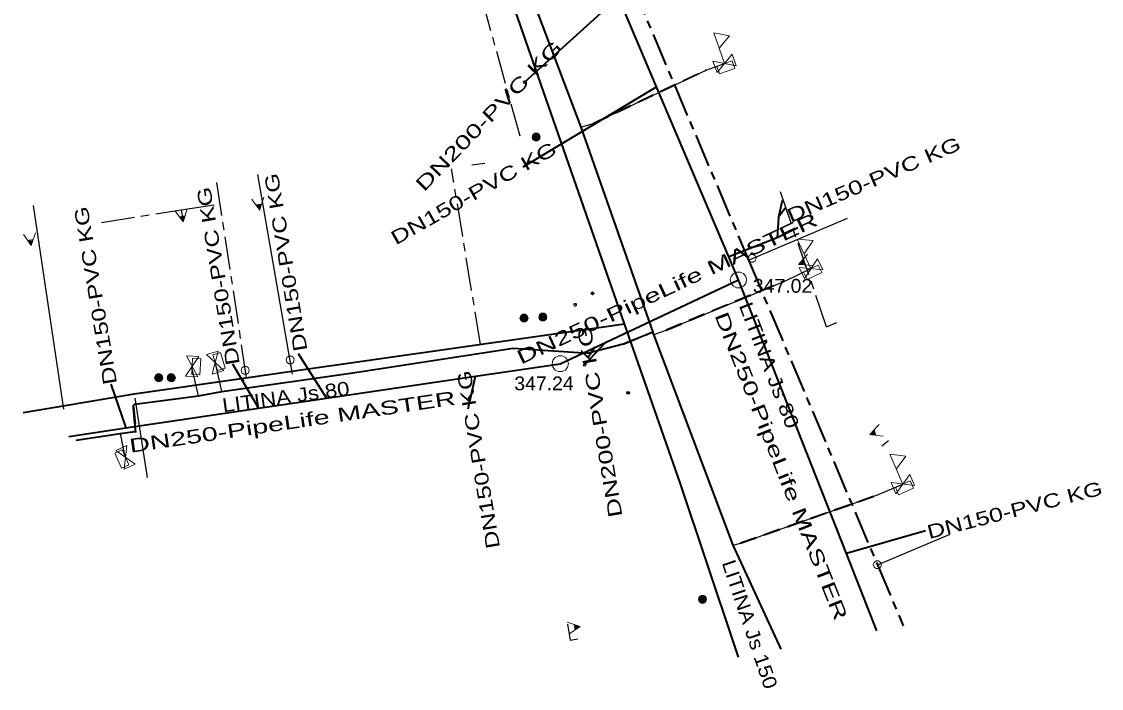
# Model space of a CAD drawing. Extents: x -763495 to -763378, y -1031793 to -1031652.
# Drawn here: x -763444.2 to -763377.8, y -1031792.8 to -1031751.8 of the extents above; entities that cross this region are included whole.
import ezdxf
from ezdxf.enums import TextEntityAlignment as Align

# ---------------------------------------------------------------- set-up
doc = ezdxf.new("R2010")
doc.units = 0
doc.header["$LTSCALE"] = 0.34
doc.header["$PDMODE"] = 32
doc.header["$PDSIZE"] = 0.17
for name, pattern in [('LONG_DASH_SHORT_DASH', [9.9, 6, -1.2, 1.5, -1.2]), ('LONG_DASHED', [7.5, 6, -1.5]), ('MEDIUM_DASHED', [4.5, 3, -1.5])]:
    doc.linetypes.add(name, pattern=pattern)
for name, color, linetype, lineweight in [('33', 7, 'Continuous', 13), ('34', 7, 'Continuous', 13), ('35', 7, 'Continuous', 13), ('37', 7, 'Continuous', 13), ('43', 7, 'Continuous', 25), ('44', 7, 'Continuous', 35), ('45', 7, 'Continuous', 13), ('47', 7, 'LONG_DASH_SHORT_DASH', 25), ('51', 7, 'LONG_DASH_SHORT_DASH', 25), ('59', 7, 'LONG_DASHED', 13)]:
    doc.layers.add(name, color=color, linetype=linetype, lineweight=lineweight)
doc.layers.add('50', color=7, linetype='Continuous')

msp = doc.modelspace()

# ---------------------------------------------------------------- linework, layer by layer
at = {"layer": '33'}
for points in [[(-763399.225, -1031766.08), (-763399.1, -1031766.17), (-763399.05, -1031766.315), (-763399.1, -1031766.46), (-763399.225, -1031766.55), (-763399.38, -1031766.55), (-763399.505, -1031766.46), (-763399.555, -1031766.315), (-763399.505, -1031766.17), (-763399.38, -1031766.08)], [(-763430.405, -1031772.97), (-763430.28, -1031773.06), (-763430.23, -1031773.205), (-763430.28, -1031773.35), (-763430.405, -1031773.44), (-763430.56, -1031773.44), (-763430.685, -1031773.35), (-763430.735, -1031773.205), (-763430.685, -1031773.06), (-763430.56, -1031772.97)], [(-763427.635, -1031772.33), (-763427.51, -1031772.42), (-763427.46, -1031772.565), (-763427.51, -1031772.71), (-763427.635, -1031772.8), (-763427.79, -1031772.8), (-763427.915, -1031772.71), (-763427.965, -1031772.565), (-763427.915, -1031772.42), (-763427.79, -1031772.33)], [(-763391.515, -1031784.93), (-763391.39, -1031785.02), (-763391.34, -1031785.165), (-763391.39, -1031785.31), (-763391.515, -1031785.4), (-763391.67, -1031785.4), (-763391.795, -1031785.31), (-763391.845, -1031785.165), (-763391.795, -1031785.02), (-763391.67, -1031784.93)]]:
    msp.add_lwpolyline(points, close=True, dxfattribs=at)
at = {"layer": '34'}
for points in [[(-763413.205, -1031755.496), (-763413.259, -1031755.565), (-763413.345, -1031755.55), (-763413.377, -1031755.466), (-763413.323, -1031755.397), (-763413.237, -1031755.412)], [(-763400.023, -1031767.161), (-763399.823, -1031767.256), (-763399.683, -1031767.431), (-763399.633, -1031767.646), (-763399.683, -1031767.861), (-763399.823, -1031768.036), (-763400.023, -1031768.131), (-763400.248, -1031768.131), (-763400.448, -1031768.036), (-763400.588, -1031767.861), (-763400.638, -1031767.646), (-763400.588, -1031767.431), (-763400.448, -1031767.256), (-763400.248, -1031767.161)], [(-763410.986, -1031772.313), (-763410.786, -1031772.408), (-763410.646, -1031772.583), (-763410.596, -1031772.798), (-763410.646, -1031773.013), (-763410.786, -1031773.188), (-763410.986, -1031773.283), (-763411.211, -1031773.283), (-763411.411, -1031773.188), (-763411.551, -1031773.013), (-763411.601, -1031772.798), (-763411.551, -1031772.583), (-763411.411, -1031772.408), (-763411.211, -1031772.313)], [(-763409.563, -1031772.788), (-763409.508, -1031772.856), (-763409.542, -1031772.937), (-763409.631, -1031772.949), (-763409.686, -1031772.882), (-763409.652, -1031772.801)]]:
    msp.add_lwpolyline(points, close=True, dxfattribs=at)
at = {"layer": '35'}
for points in [[(-763400.992, -1031754.326), (-763401.659, -1031752.44), (-763400.691, -1031752.628), (-763401.325, -1031753.383)], [(-763395.676, -1031766.945), (-763396.528, -1031765.135), (-763395.546, -1031765.226), (-763396.102, -1031766.04)], [(-763390.029, -1031780.201), (-763390.826, -1031778.367), (-763389.847, -1031778.487), (-763390.428, -1031779.284)]]:
    msp.add_lwpolyline(points, dxfattribs=at)
for points in [[(-763401.706, -1031754.181), (-763401.456, -1031754.888), (-763400.528, -1031753.764), (-763400.278, -1031754.471)], [(-763396.401, -1031766.872), (-763396.082, -1031767.55), (-763395.27, -1031766.34), (-763394.951, -1031767.018)], [(-763432.144, -1031772.024), (-763432.862, -1031772.239), (-763431.786, -1031773.221), (-763432.504, -1031773.436)], [(-763433.335, -1031772.35), (-763434.084, -1031772.313), (-763433.396, -1031773.599), (-763434.145, -1031773.562)], [(-763437.923, -1031779.28), (-763437.241, -1031778.968), (-763438.443, -1031778.144), (-763437.761, -1031777.832)], [(-763390.752, -1031780.106), (-763390.453, -1031780.794), (-763389.605, -1031779.608), (-763389.306, -1031780.296)]]:
    msp.add_lwpolyline(points, close=True, dxfattribs=at)
at = {"layer": '37'}
for points in [[(-763412.655, -1031758.62), (-763412.5, -1031758.62), (-763412.375, -1031758.71), (-763412.325, -1031758.855), (-763412.375, -1031759), (-763412.5, -1031759.09), (-763412.655, -1031759.09), (-763412.78, -1031759), (-763412.83, -1031758.855), (-763412.78, -1031758.71), (-763412.655, -1031758.62), (-763412.64, -1031758.64), (-763412.52, -1031758.64), (-763412.44, -1031758.68), (-763412.72, -1031758.68), (-763412.76, -1031758.72), (-763412.4, -1031758.72), (-763412.4, -1031758.76), (-763412.76, -1031758.76), (-763412.78, -1031758.8), (-763412.38, -1031758.8), (-763412.36, -1031758.84), (-763412.8, -1031758.84), (-763412.8, -1031758.88), (-763412.36, -1031758.88), (-763412.375, -1031758.92), (-763412.78, -1031758.92), (-763412.775, -1031758.96), (-763412.37, -1031758.96), (-763412.395, -1031759), (-763412.755, -1031759), (-763412.715, -1031759.04), (-763412.435, -1031759.04), (-763412.49, -1031759.08), (-763412.66, -1031759.08)], [(-763429.34, -1031762.549), (-763429.548, -1031763.222), (-763429.587, -1031763.35), (-763430.001, -1031762.78), (-763430.08, -1031762.671)], [(-763429.817, -1031763.033), (-763429.472, -1031762.976), (-763429.503, -1031763.001), (-763429.779, -1031763.047), (-763429.733, -1031763.08), (-763429.516, -1031763.044), (-763429.53, -1031763.087), (-763429.727, -1031763.12), (-763429.701, -1031763.156), (-763429.548, -1031763.13), (-763429.556, -1031763.172), (-763429.674, -1031763.192), (-763429.648, -1031763.228), (-763429.564, -1031763.214), (-763429.582, -1031763.258), (-763429.622, -1031763.264), (-763429.595, -1031763.301)], [(-763434.04, -1031763.28), (-763434.25, -1031763.952), (-763434.289, -1031764.08), (-763434.702, -1031763.509), (-763434.78, -1031763.4)], [(-763434.518, -1031763.763), (-763434.173, -1031763.707), (-763434.204, -1031763.732), (-763434.481, -1031763.777), (-763434.435, -1031763.81), (-763434.218, -1031763.775), (-763434.231, -1031763.817), (-763434.428, -1031763.85), (-763434.402, -1031763.886), (-763434.249, -1031763.861), (-763434.258, -1031763.903), (-763434.376, -1031763.922), (-763434.35, -1031763.958), (-763434.266, -1031763.945), (-763434.284, -1031763.988), (-763434.324, -1031763.995), (-763434.298, -1031764.031)], [(-763443.369, -1031764.738), (-763443.594, -1031765.406), (-763443.637, -1031765.533), (-763444.035, -1031764.952), (-763444.111, -1031764.842)], [(-763443.858, -1031765.21), (-763443.511, -1031765.162), (-763443.543, -1031765.187), (-763443.821, -1031765.225), (-763443.776, -1031765.259), (-763443.558, -1031765.229), (-763443.572, -1031765.271), (-763443.77, -1031765.299), (-763443.745, -1031765.336), (-763443.591, -1031765.315), (-763443.601, -1031765.356), (-763443.719, -1031765.373), (-763443.694, -1031765.41), (-763443.61, -1031765.398), (-763443.629, -1031765.441), (-763443.669, -1031765.446), (-763443.643, -1031765.483)], [(-763395.611, -1031766.758), (-763396.313, -1031766.7), (-763396.446, -1031766.688), (-763395.978, -1031766.162), (-763395.889, -1031766.062)], [(-763396.186, -1031766.396), (-763396.056, -1031766.721), (-763396.088, -1031766.696), (-763396.192, -1031766.436), (-763396.214, -1031766.488), (-763396.133, -1031766.692), (-763396.177, -1031766.688), (-763396.251, -1031766.503), (-763396.281, -1031766.536), (-763396.224, -1031766.68), (-763396.266, -1031766.681), (-763396.311, -1031766.57), (-763396.341, -1031766.603), (-763396.309, -1031766.682), (-763396.355, -1031766.674), (-763396.37, -1031766.636), (-763396.4, -1031766.67)], [(-763413.405, -1031769.76), (-763413.25, -1031769.76), (-763413.125, -1031769.85), (-763413.075, -1031769.995), (-763413.125, -1031770.14), (-763413.25, -1031770.23), (-763413.405, -1031770.23), (-763413.53, -1031770.14), (-763413.58, -1031769.995), (-763413.53, -1031769.85), (-763413.405, -1031769.76), (-763413.39, -1031769.78), (-763413.27, -1031769.78), (-763413.19, -1031769.82), (-763413.47, -1031769.82), (-763413.51, -1031769.86), (-763413.15, -1031769.86), (-763413.15, -1031769.9), (-763413.51, -1031769.9), (-763413.53, -1031769.94), (-763413.13, -1031769.94), (-763413.11, -1031769.98), (-763413.55, -1031769.98), (-763413.55, -1031770.02), (-763413.11, -1031770.02), (-763413.125, -1031770.06), (-763413.53, -1031770.06), (-763413.525, -1031770.1), (-763413.12, -1031770.1), (-763413.145, -1031770.14), (-763413.505, -1031770.14), (-763413.465, -1031770.18), (-763413.185, -1031770.18), (-763413.24, -1031770.22), (-763413.41, -1031770.22)], [(-763412.245, -1031769.69), (-763412.09, -1031769.69), (-763411.965, -1031769.78), (-763411.915, -1031769.925), (-763411.965, -1031770.07), (-763412.09, -1031770.16), (-763412.245, -1031770.16), (-763412.37, -1031770.07), (-763412.42, -1031769.925), (-763412.37, -1031769.78), (-763412.245, -1031769.69), (-763412.23, -1031769.71), (-763412.11, -1031769.71), (-763412.03, -1031769.75), (-763412.31, -1031769.75), (-763412.35, -1031769.79), (-763411.99, -1031769.79), (-763411.99, -1031769.83), (-763412.35, -1031769.83), (-763412.37, -1031769.87), (-763411.97, -1031769.87), (-763411.95, -1031769.91), (-763412.39, -1031769.91), (-763412.39, -1031769.95), (-763411.95, -1031769.95), (-763411.965, -1031769.99), (-763412.37, -1031769.99), (-763412.365, -1031770.03), (-763411.96, -1031770.03), (-763411.985, -1031770.07), (-763412.345, -1031770.07), (-763412.305, -1031770.11), (-763412.025, -1031770.11), (-763412.08, -1031770.15), (-763412.25, -1031770.15)], [(-763435.875, -1031773.43), (-763435.72, -1031773.43), (-763435.595, -1031773.52), (-763435.545, -1031773.665), (-763435.595, -1031773.81), (-763435.72, -1031773.9), (-763435.875, -1031773.9), (-763436, -1031773.81), (-763436.05, -1031773.665), (-763436, -1031773.52), (-763435.875, -1031773.43), (-763435.86, -1031773.45), (-763435.74, -1031773.45), (-763435.66, -1031773.49), (-763435.94, -1031773.49), (-763435.98, -1031773.53), (-763435.62, -1031773.53), (-763435.62, -1031773.57), (-763435.98, -1031773.57), (-763436, -1031773.61), (-763435.6, -1031773.61), (-763435.58, -1031773.65), (-763436.02, -1031773.65), (-763436.02, -1031773.69), (-763435.58, -1031773.69), (-763435.595, -1031773.73), (-763436, -1031773.73), (-763435.995, -1031773.77), (-763435.59, -1031773.77), (-763435.615, -1031773.81), (-763435.975, -1031773.81), (-763435.935, -1031773.85), (-763435.655, -1031773.85), (-763435.71, -1031773.89), (-763435.88, -1031773.89)], [(-763435.105, -1031773.43), (-763434.95, -1031773.43), (-763434.825, -1031773.52), (-763434.775, -1031773.665), (-763434.825, -1031773.81), (-763434.95, -1031773.9), (-763435.105, -1031773.9), (-763435.23, -1031773.81), (-763435.28, -1031773.665), (-763435.23, -1031773.52), (-763435.105, -1031773.43), (-763435.09, -1031773.45), (-763434.97, -1031773.45), (-763434.89, -1031773.49), (-763435.17, -1031773.49), (-763435.21, -1031773.53), (-763434.85, -1031773.53), (-763434.85, -1031773.57), (-763435.21, -1031773.57), (-763435.23, -1031773.61), (-763434.83, -1031773.61), (-763434.81, -1031773.65), (-763435.25, -1031773.65), (-763435.25, -1031773.69), (-763434.81, -1031773.69), (-763434.825, -1031773.73), (-763435.23, -1031773.73), (-763435.225, -1031773.77), (-763434.82, -1031773.77), (-763434.845, -1031773.81), (-763435.205, -1031773.81), (-763435.165, -1031773.85), (-763434.885, -1031773.85), (-763434.94, -1031773.89), (-763435.11, -1031773.89)], [(-763391.233, -1031777.253), (-763391.932, -1031777.17), (-763392.065, -1031777.155), (-763391.58, -1031776.644), (-763391.487, -1031776.547)], [(-763391.796, -1031776.871), (-763391.677, -1031777.2), (-763391.708, -1031777.174), (-763391.803, -1031776.911), (-763391.827, -1031776.962), (-763391.752, -1031777.169), (-763391.796, -1031777.164), (-763391.864, -1031776.976), (-763391.895, -1031777.008), (-763391.842, -1031777.154), (-763391.885, -1031777.153), (-763391.926, -1031777.04), (-763391.957, -1031777.073), (-763391.928, -1031777.153), (-763391.974, -1031777.143), (-763391.988, -1031777.105), (-763392.018, -1031777.138)], [(-763402.425, -1031787.05), (-763402.27, -1031787.05), (-763402.145, -1031787.14), (-763402.095, -1031787.285), (-763402.145, -1031787.43), (-763402.27, -1031787.52), (-763402.425, -1031787.52), (-763402.55, -1031787.43), (-763402.6, -1031787.285), (-763402.55, -1031787.14), (-763402.425, -1031787.05), (-763402.41, -1031787.07), (-763402.29, -1031787.07), (-763402.21, -1031787.11), (-763402.49, -1031787.11), (-763402.53, -1031787.15), (-763402.17, -1031787.15), (-763402.17, -1031787.19), (-763402.53, -1031787.19), (-763402.55, -1031787.23), (-763402.15, -1031787.23), (-763402.13, -1031787.27), (-763402.57, -1031787.27), (-763402.57, -1031787.31), (-763402.13, -1031787.31), (-763402.145, -1031787.35), (-763402.55, -1031787.35), (-763402.545, -1031787.39), (-763402.14, -1031787.39), (-763402.165, -1031787.43), (-763402.525, -1031787.43), (-763402.485, -1031787.47), (-763402.205, -1031787.47), (-763402.26, -1031787.51), (-763402.43, -1031787.51)], [(-763410.667, -1031788.699), (-763409.996, -1031788.915), (-763409.869, -1031788.957), (-763410.444, -1031789.363), (-763410.553, -1031789.441)], [(-763410.188, -1031789.183), (-763410.241, -1031788.837), (-763410.216, -1031788.868), (-763410.174, -1031789.145), (-763410.14, -1031789.099), (-763410.173, -1031788.882), (-763410.131, -1031788.896), (-763410.101, -1031789.093), (-763410.064, -1031789.067), (-763410.088, -1031788.914), (-763410.046, -1031788.923), (-763410.028, -1031789.042), (-763409.991, -1031789.016), (-763410.004, -1031788.932), (-763409.961, -1031788.95), (-763409.955, -1031788.99), (-763409.918, -1031788.964)]]:
    msp.add_lwpolyline(points, dxfattribs=at)
at = {"layer": '43', "linetype": 'LONG_DASH_SHORT_DASH'}
for p, q in [((-763416.002, -1031771.613), (-763417.782, -1031760.8)), ((-763430.39, -1031773.66), (-763432.22, -1031761.62))]:
    msp.add_line(p, q, dxfattribs=at)
at = {"layer": '43'}
for p, q in [((-763427.57, -1031773.45), (-763429.71, -1031761.15)), ((-763441.64, -1031775.59), (-763443.5, -1031763.07)), ((-763399.52, -1031766.42), (-763393.43, -1031763.84)), ((-763430.56, -1031773.91), (-763430.59, -1031773.69)), ((-763437.27, -1031774.92), (-763436.5, -1031779.792)), ((-763391.59, -1031785.17), (-763387.11, -1031783.28))]:
    msp.add_line(p, q, dxfattribs=at)
at = {"layer": '43', "lineweight": 35}
for points in [[(-763400.132, -1031790.86), (-763400.38, -1031790.12), (-763403.73, -1031780.13), (-763407.14, -1031770.35), (-763416.343, -1031743.922), (-763410.726, -1031739.937), (-763410.479, -1031739.762)], [(-763444.127, -1031775.807), (-763441.67, -1031775.39), (-763437.31, -1031774.66), (-763430.59, -1031773.69), (-763427.6, -1031773.26), (-763407.14, -1031770.35)]]:
    msp.add_lwpolyline(points, dxfattribs=at)
at = {"layer": '43', "linetype": 'LONG_DASH_SHORT_DASH', "lineweight": 35}
msp.add_lwpolyline([(-763410.726, -1031739.937), (-763410.61, -1031740.22), (-763406.7, -1031749.44), (-763399.52, -1031766.42), (-763391.59, -1031785.17), (-763390, -1031788.925)], dxfattribs=at)
at = {"layer": '44'}
for p, q in [((-763413.291, -1031755.481), (-763407.519, -1031750.23)), ((-763413.385, -1031760.681), (-763405.172, -1031755.763)), ((-763397.266, -1031763.229), (-763397.674, -1031763.789)), ((-763409.597, -1031772.869), (-763408.309, -1031771.488)), ((-763427.23, -1031772.166), (-763425.477, -1031774.924)), ((-763431.26, -1031772.812), (-763429.652, -1031775.541)), ((-763416.771, -1031775.575), (-763416.317, -1031773.57)), ((-763438.74, -1031774.059), (-763437.823, -1031776.75)), ((-763388.634, -1031783.087), (-763393.492, -1031784.483))]:
    msp.add_line(p, q, dxfattribs=at)
for points in [[(-763391.618, -1031789.234), (-763393.492, -1031784.483), (-763400.133, -1031767.646), (-763400.737, -1031766.222), (-763405.172, -1031755.763), (-763407.519, -1031750.23), (-763407.897, -1031749.337), (-763411.012, -1031744.81), (-763417.435, -1031735.477), (-763425.031, -1031724.437), (-763457.995, -1031686.981)], [(-763397.452, -1031762.75), (-763397.674, -1031763.789), (-763397.755, -1031765.048)], [(-763396.479, -1031764.447), (-763397.755, -1031765.048), (-763400.737, -1031766.222)], [(-763441.329, -1031777.268), (-763437.823, -1031776.75), (-763429.652, -1031775.541), (-763425.477, -1031774.924), (-763416.317, -1031773.57), (-763411.096, -1031772.798), (-763400.133, -1031767.646)]]:
    msp.add_lwpolyline(points, dxfattribs=at)
at = {"layer": '45', "linetype": 'MEDIUM_DASHED'}
for p, q in [((-763409.096, -1031757.994), (-763402.137, -1031754.694)), ((-763409.079, -1031758.03), (-763402.12, -1031754.73)), ((-763409.062, -1031758.066), (-763402.103, -1031754.766)), ((-763404.595, -1031770.693), (-763397.305, -1031767.673)), ((-763404.58, -1031770.73), (-763397.29, -1031767.71)), ((-763404.565, -1031770.767), (-763397.275, -1031767.747)), ((-763407.245, -1031771.563), (-763405.704, -1031770.933)), ((-763407.23, -1031771.6), (-763405.689, -1031770.97)), ((-763407.215, -1031771.637), (-763405.674, -1031771.007)), ((-763437.393, -1031775.48), (-763437.27, -1031776.862)), ((-763437.348, -1031775.476), (-763437.225, -1031776.858)), ((-763437.303, -1031775.472), (-763437.18, -1031776.854)), ((-763400.032, -1031783.802), (-763391.633, -1031780.852)), ((-763400.019, -1031783.84), (-763391.62, -1031780.89)), ((-763400.006, -1031783.878), (-763391.607, -1031780.928))]:
    msp.add_line(p, q, dxfattribs=at)
at = {"layer": '45', "lineweight": 35}
for points in [[(-763414.95, -1031744.87), (-763414.41, -1031746.14), (-763409.84, -1031758.25), (-763405.4, -1031770.86)], [(-763405.4, -1031770.86), (-763405.689, -1031770.97), (-763407.23, -1031771.6), (-763409.364, -1031772.149)], [(-763397.504, -1031790.358), (-763400.46, -1031783.97), (-763405.337, -1031771.01), (-763405.4, -1031770.86)], [(-763440.885, -1031777.5), (-763438.168, -1031777.084), (-763437.275, -1031776.978), (-763437.209, -1031776.997), (-763437.225, -1031776.858), (-763437.348, -1031775.476), (-763437.37, -1031775.391), (-763437.273, -1031775.284), (-763433.36, -1031774.772), (-763431.913, -1031774.504), (-763423.866, -1031773.351), (-763414, -1031771.837), (-763409.364, -1031772.149)]]:
    msp.add_lwpolyline(points, dxfattribs=at)
at = {"layer": '45', "lineweight": 25}
for points in [[(-763409.84, -1031758.25), (-763409.079, -1031758.03), (-763402.12, -1031754.73), (-763400.992, -1031754.326)], [(-763405.337, -1031771.01), (-763404.58, -1031770.73), (-763397.29, -1031767.71), (-763395.676, -1031766.945)], [(-763433.36, -1031774.772), (-763433.748, -1031773.104), (-763433.74, -1031772.956)], [(-763431.913, -1031774.504), (-763432.286, -1031772.855), (-763432.324, -1031772.73)], [(-763438.168, -1031777.084), (-763437.903, -1031778.424), (-763437.842, -1031778.556)], [(-763400.46, -1031783.97), (-763400.019, -1031783.84), (-763391.62, -1031780.89), (-763390.029, -1031780.201)]]:
    msp.add_lwpolyline(points, dxfattribs=at)
at = {"layer": '45'}
for points in [[(-763400.992, -1031754.326), (-763400.521, -1031754.159), (-763400.353, -1031754.63), (-763401.296, -1031754.965), (-763401.463, -1031754.493)], [(-763395.676, -1031766.945), (-763395.224, -1031766.731), (-763395.01, -1031767.183), (-763395.914, -1031767.611), (-763396.128, -1031767.159)], [(-763432.324, -1031772.73), (-763432.467, -1031772.251), (-763431.988, -1031772.108), (-763431.702, -1031773.066), (-763432.181, -1031773.209)], [(-763433.74, -1031772.956), (-763433.715, -1031772.457), (-763433.216, -1031772.481), (-763433.265, -1031773.48), (-763433.765, -1031773.455)], [(-763437.842, -1031778.556), (-763437.634, -1031779.011), (-763438.089, -1031779.219), (-763438.505, -1031778.309), (-763438.05, -1031778.101)], [(-763390.029, -1031780.201), (-763389.571, -1031780.001), (-763389.371, -1031780.459), (-763390.287, -1031780.859), (-763390.487, -1031780.401)]]:
    msp.add_lwpolyline(points, close=True, dxfattribs=at)
at = {"layer": '47'}
for p, q in [((-763416.535, -1031760.565), (-763415.742, -1031760.459)), ((-763394.713, -1031770.522), (-763397.592, -1031762.13)), ((-763434.41, -1031763.34), (-763434.329, -1031763.833)), ((-763394.713, -1031770.522), (-763394.087, -1031770.257)), ((-763391.311, -1031777.841), (-763390.915, -1031777.522))]:
    msp.add_line(p, q, dxfattribs=at)
for points in [[(-763439.309, -1031764.101), (-763434.41, -1031763.34), (-763432.06, -1031762.975)], [(-763410.648, -1031788.824), (-763410.499, -1031789.812), (-763410.008, -1031789.716)]]:
    msp.add_lwpolyline(points, dxfattribs=at)
at = {"layer": '50'}
for p in [(-763409.118, -1031768.467), (-763406.914, -1031774.593)]:
    msp.add_point(p, dxfattribs=at)
at = {"layer": '51'}
msp.add_lwpolyline([(-763413.57, -1031758.8), (-763416.497, -1031748.207), (-763418.78, -1031745.488), (-763420.771, -1031744.021), (-763423.544, -1031742.877), (-763426.98, -1031742.31)], dxfattribs=at)
at = {"layer": '59'}
msp.add_point((-763410.18, -1031769.17), dxfattribs=at)

# ---------------------------------------------------------------- texts
at = {"layer": '33'}
for s, rotation, width, p in [('LITINA Js 80', 291.177, 1.25, (-763398.64, -1031773.043)), ('LITINA Js 80', 7.792, 1.2, (-763427.922, -1031775.252)), ('LITINA Js 150', 288.713, 1.15, (-763399.844, -1031788.966))]:
    msp.add_text(s, height=0.85, rotation=rotation, dxfattribs=dict(at, width=width)).set_placement(p, align=Align.CENTER)
at = {"layer": '44'}
for s, rotation, width, p in [('DN200-PVC KG', 45.894, 1.5, (-763415.188, -1031757.835)), ('DN150-PVC KG', 23.377, 1.4, (-763391.641, -1031761.858)), ('DN150-PVC KG', 29.679, 1.4, (-763416.215, -1031762.674)), ('DN150-PVC KG', 99.465, 1.35, (-763427.56, -1031766.493)), ('DN150-PVC KG', 99.465, 1.35, (-763431.721, -1031767.339)), ('DN150-PVC KG', 99.465, 1.35, (-763439.267, -1031768.539)), ('DN250-PipeLife MASTER', 25.153, 1.55, (-763404.343, -1031768.552)), ('DN250-PipeLife MASTER', 291.532, 1.55, (-763397.901, -1031779.248)), ('DN200-PVC KG', 99.465, 1.45, (-763408.25, -1031776.302)), ('DN150-PVC KG', 99.465, 1.35, (-763415.713, -1031778.628)), ('DN250-PipeLife MASTER', 8.422, 1.55, (-763427.515, -1031776.795)), ('DN150-PVC KG', 14.381, 1.35, (-763383.037, -1031782.211))]:
    msp.add_text(s, height=0.85, rotation=rotation, dxfattribs=dict(at, width=width)).set_placement(p, align=Align.CENTER)
at = {"layer": '44', "width": 1.05}
for s, p in [('347.02', (-763397.424, -1031768.433)), ('347.24', (-763412.1, -1031774.432))]:
    msp.add_text(s, height=0.85, dxfattribs=at).set_placement(p, align=Align.CENTER)

doc.saveas('drawing.dxf')
